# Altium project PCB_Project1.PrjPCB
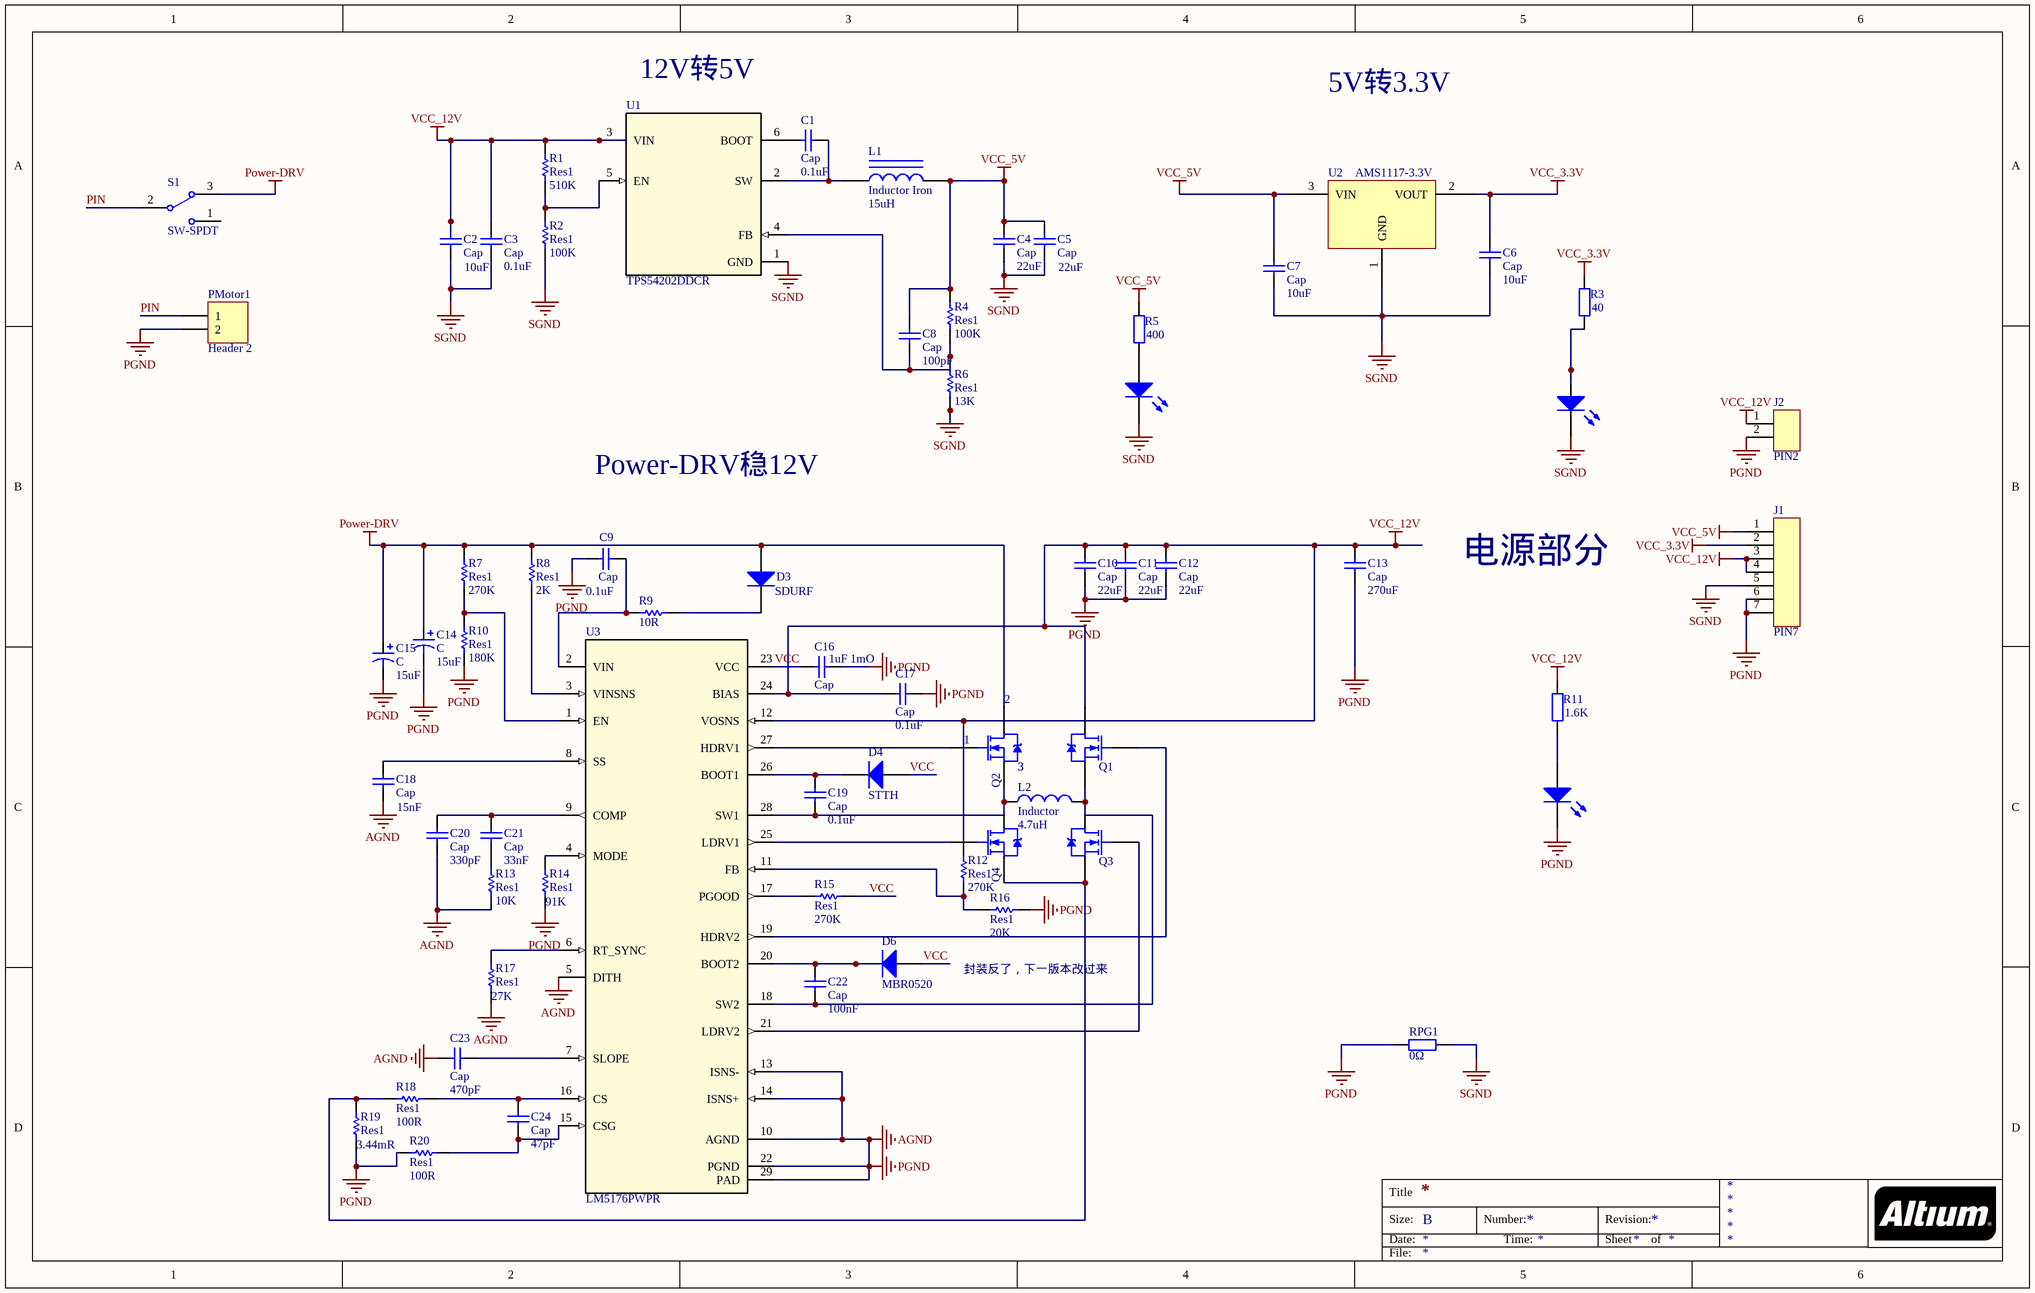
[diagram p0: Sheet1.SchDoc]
1 sheet, 64 parts. Net scope: global (net labels, ports and power ports of the same name join across sheets).
Board file: power-manage.PcbDoc

## Sheet Sheet1.SchDoc
size B

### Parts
C1  Cap  value 0.1uF  [0402-C]
C2  Cap  value 10uF  [1206-C]
C3  Cap  value 0.1uF  [0402-C]
C4  Cap  value 22uF  [0805-C]
C5  Cap  value 22uF  [0805-C]
C6  Cap  value 10uF  [0603-C]
C7  Cap  value 10uF  [0603-C]
C8  Cap  value 100pF  [0402-C]
C9  Cap  value 0.1uF  [0603-C]
C10  Cap  value 22uF  [1206-C]
C11  Cap  value 22uF  [1206-C]
C12  Cap  value 22uF  [1206-C]
C13  Cap  value 270uF  [CAP-E SMD 6.6X6.6]
C14  C  value 15uF  [C2220]
C15  C  value 15uF  [C2220]
C16  Cap  value 1uF 1mO  [C0402]
C17  Cap  value 0.1uF  [0402-C]
C18  Cap  value 15nF  [0402-C]
C19  Cap  value 0.1uF  [0603-C]
C20  Cap  value 330pF  [C0402]
C21  Cap  value 33nF  [C0402]
C22  Cap  value 100nF  [C0603]
C23  Cap  value 470pF  [0402-C]
C24  Cap  value 47pF  [0603-C]
D1  LED0  [LED0805]  (value not drawn)
D2  LED0  [LED0805]  (value not drawn)
D3  SDURF  [TO-220-AS]
D4  STTH  [TO-220-AS]
D5  LED0  [LED0805]  (value not drawn)
D6  MBR0520  [SOD-123]
J1  PIN7  [XH7-2.54]
J2  PIN2  [XH2-2.54]
L1  Inductor Iron  value 15uH  [IND-SMD_L7.8-W7.0_MAPM0630F]
L2  Inductor  value 4.7uH  [IND-SMD_L13.8-W12.6_MHCC12050]
PMotor1  Header 2  [PCBComponent_1]
Q1  NCE  [TO252]  (value not drawn)
Q2  BSC117  [BSC010N04LS6ATMA1]  (value not drawn)
Q3  NCE  [TO252]  (value not drawn)
Q4  BSC037  [BSC010N04LS6ATMA1]  (value not drawn)
R1  Res1  value 510K  [0603-R]
R2  Res1  value 100K  [0603-R]
R3  value 40  [R0603]  (hidden comment: Res2)
R4  Res1  value 100K  [0603-R]
R5  value 400  [R0603]  (hidden comment: Res2)
R6  Res1  value 13K  [0603-R]
R7  Res1  value 270K  [0603-R]
R8  Res1  value 2K  [0603-R]
R9  10R  [0603-R]
R10  Res1  value 180K  [0603-R]
R11  value 1.6K  [R0603]  (hidden comment: Res2)
R12  Res1  value 270K  [0603-R]
R13  Res1  value 10K  [0603-R]
R14  Res1  value 91K  [0603-R]
R15  Res1  value 270K  [0603-R]
R16  Res1  value 20K  [0603-R]
R17  Res1  value 27K  [R0603]
R18  Res1  value 100R  [0603-R]
R19  Res1  value 3.44mR  [2512-R]
R20  Res1  value 100R  [0603-R]
RPG1  value 0Ω  [R1206]  (hidden comment: Res2)
S1  SW-SPDT  [SW-TO3]
U1  TPS54202DDCR  [DDC0006A_N]
U2  AMS1117-3.3V  [SOT223]
U3  LM5176PWPR  [PWP0028C_N]

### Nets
AGND: C9.1 C10.2 C11.2 C12.2 C13.1 C14.2 C15.2 C16.2 C17.2 C18.2 C20.2 C23.1 D5.2(K) J1.6 J1.7 J2.2 PMotor1.2 R10.1 R13.1 R14.1 R16.2 R17.1 R19.1 R20.1 RPG1.2 U3.5(DITH) U3.10(AGND) U3.13(ISNS-) U3.14(ISNS+) U3.22(PGND) U3.29(PAD)  [also labelled PGND]
Power-DRV: C14.1 C15.1 D3.1(A) Q2.2(D) R7.2 R8.2 S1.3
SGND: C2.1 C3.1 C4.2 C5.2 C6.1 C7.1 D1.2(K) D2.2(K) J1.5 R2.1 R6.1 RPG1.1 U1.1(GND) U2.1(GND)
VCC_3.3V: C6.2 J1.2 R3.2 U2.2(VOUT)
VCC_5V: C4.1 C5.1 C7.2 C8.1 J1.1 L1.2 R4.2 R5.2 U2.3(VIN)
VCC_12V: C2.2 C3.2 C10.1 C11.1 C12.1 C13.2 C17.1 J1.3 J1.4 J2.1 Q1.2(D) R1.2 R11.2 R12.2 U1.3(VIN) U3.12(VOSNS) U3.24(BIAS)
PIN: PMotor1.1 S1.2
VCC: C16.1 D4.1(A) D6.1(A) R15.2 U3.23(VCC)
NetC1_1: C1.1 L1.1 U1.2(SW)
NetC1_2: C1.2 U1.6(BOOT)
NetC8_2: C8.2 R4.1 R6.2 U1.4(FB)
NetC9_2: C9.2 R9.1 U3.2(VIN)
NetC18_1: C18.1 U3.8(SS)
NetC19_1: C19.1 L2.1 Q2.3(S) Q4.2(D) U3.28(SW1)
NetC19_2: C19.2 D4.2(K) U3.26(BOOT1)
NetC20_1: C20.1 C21.1 U3.9(COMP)
NetC21_2: C21.2 R13.2
NetC22_1: C22.1 L2.2 Q1.3(S) Q3.2(D) U3.18(SW2)
NetC22_2: C22.2 D6.2(K) U3.20(BOOT2)
NetC23_2: C23.2 U3.7(SLOPE)
NetC24_1: C24.1 R18.2 U3.16(CS)
NetC24_2: C24.2 R20.2 U3.15(CSG)
NetD1_1: D1.1(A) R5.1
NetD2_1: D2.1(A) R3.1
NetD3_2: D3.2(K) R9.2
NetD5_1: D5.1(A) R11.1
NetQ1_1: Q1.1(G) U3.19(HDRV2)
NetQ2_1: Q2.1(G) U3.27(HDRV1)
NetQ3_1: Q3.1(G) U3.21(LDRV2)
NetQ3_3: Q3.3(S) Q4.3(S) R18.1 R19.2
NetQ4_1: Q4.1(G) U3.25(LDRV1)
NetR1_1: R1.1 R2.2 U1.5(EN)
NetR7_1: R7.1 R10.2 U3.1(EN)
NetR8_1: R8.1 U3.3(VINSNS)
NetR12_1: R12.1 R16.1 U3.11(FB)
NetR14_2: R14.2 U3.4(MODE)
NetR15_1: R15.1 U3.17(PGOOD)
NetR17_2: R17.2 U3.6(RT_SYNC)

Not connected (* = marked no-connect by the designer): S1 1

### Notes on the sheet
- 12V转5V
- 5V转3.3V
- Power-DRV稳12V
- 电源部分
- (near Q2) 2
- (near Q2) 1
- (near Q2) 3
- 封装反了，下一版本改过来

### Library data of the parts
C1-C13 C16-C24 = Cap: Capacitor
C14 C15 = Cap Pol1: Polarized Capacitor (Radial)
D1 D2 D5 = LED0: Typical INFRARED GaAs LED
D3 D4 D6 = Diode 1N4003: 1 Amp General Purpose Rectifier
L1 = Inductor Iron: Magnetic-Core Inductor
L2 = Inductor: Code_IEC: 1005
PMotor1 = Header 2: Header, 2-Pin
Q1-Q4 = NMOS-2: N-Channel Power MOSFET; Note: Pin 2 is electrically connected to pin 4.
R1 R2 R4 R6-R10 R12-R20 = Res1: Resistor
R3 R5 R11 RPG1 = Res2: Resistor
S1 = SW-SPDT: SPDT Subminiature Toggle Switch, Right Angle Mounting, Vertical Actuation
U1 = TPS54202DDCR: No Description Available; Manufacturer: Texas Instruments
U2 = AMS1117
U3 = LM5176PWPR: No Description Available; Manufacturer: Texas Instruments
